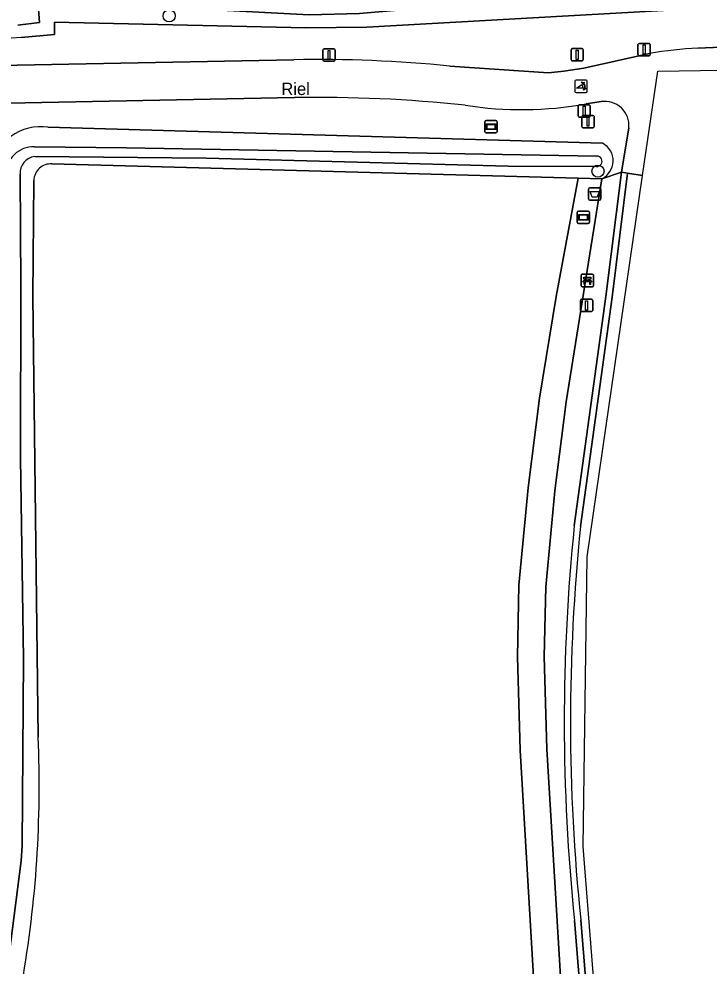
# Model space of a CAD drawing. Extents: x 163426 to 164192, y 380329 to 381641.
# Drawn here: x 164054.4 to 164110, y 380946 to 381022.4 of the extents above; entities that cross this region are included whole.
import ezdxf

# ---------------------------------------------------------------- set-up
doc = ezdxf.new("R2010")
doc.units = 0
for name, color, linetype in [('IMGEO_Afsluitpaal', 7, 'Continuous'), ('IMGEO_Afvalbak', 7, 'Continuous'), ('IMGEO_Bank', 7, 'Continuous'), ('IMGEO_Berm_halfverhard', 7, 'Continuous'), ('IMGEO_Boom', 7, 'Continuous'), ('IMGEO_Erf', 7, 'Continuous'), ('IMGEO_Fietspad_gesloten', 7, 'Continuous'), ('IMGEO_Fietspad_open', 7, 'Continuous'), ('IMGEO_Grasland_overig', 7, 'Continuous'), ('IMGEO_Groenvoorziening', 7, 'Continuous'), ('IMGEO_Informatiebord', 7, 'Continuous'), ('IMGEO_Lichtmast', 7, 'Continuous'), ('IMGEO_Loofbos', 7, 'Continuous'), ('IMGEO_Oever', 7, 'Continuous'), ('IMGEO_Openbare_ruimte_label', 7, 'Continuous'), ('IMGEO_Poller', 7, 'Continuous'), ('IMGEO_Verkeersbordpaal', 7, 'Continuous'), ('IMGEO_Waterloop', 7, 'Continuous'), ('IMGEO_Wegwijzer', 7, 'Continuous')]:
    doc.layers.add(name, color=color, linetype=linetype)

msp = doc.modelspace()

# ---------------------------------------------------------------- linework, layer by layer
at = {"layer": 'IMGEO_Afsluitpaal'}
for p, q in [((164098.925, 381019.065), (164098.925, 381019.865)), ((164098.925, 381019.865), (164098.925, 381019.065)), ((164099.025, 381019.965), (164099.815, 381019.965)), ((164099.815, 381019.965), (164099.025, 381019.965)), ((164099.915, 381019.865), (164099.915, 381019.065)), ((164099.915, 381019.065), (164099.915, 381019.865)), ((164099.815, 381018.965), (164099.025, 381018.965)), ((164099.025, 381018.965), (164099.815, 381018.965)), ((164099.491, 381014.542), (164099.491, 381015.342)), ((164099.491, 381015.342), (164099.491, 381014.542)), ((164099.591, 381015.442), (164100.381, 381015.442)), ((164100.381, 381015.442), (164099.591, 381015.442)), ((164100.481, 381015.342), (164100.481, 381014.542)), ((164100.481, 381014.542), (164100.481, 381015.342)), ((164100.381, 381014.442), (164099.591, 381014.442)), ((164099.591, 381014.442), (164100.381, 381014.442)), ((164099.796, 381013.683), (164099.796, 381014.483)), ((164099.796, 381014.483), (164099.796, 381013.683)), ((164099.896, 381014.583), (164100.686, 381014.583)), ((164100.686, 381014.583), (164099.896, 381014.583)), ((164100.786, 381014.483), (164100.786, 381013.683)), ((164100.786, 381013.683), (164100.786, 381014.483)), ((164100.686, 381013.583), (164099.896, 381013.583)), ((164099.896, 381013.583), (164100.686, 381013.583))]:
    msp.add_line(p, q, dxfattribs=at)
for points in [[(164099.345, 381019.84), (164099.495, 381019.84), (164099.495, 381019.09), (164099.345, 381019.09), (164099.345, 381019.84)], [(164099.911, 381015.317), (164100.061, 381015.317), (164100.061, 381014.567), (164099.911, 381014.567), (164099.911, 381015.317)], [(164100.216, 381014.458), (164100.366, 381014.458), (164100.366, 381013.708), (164100.216, 381013.708), (164100.216, 381014.458)]]:
    msp.add_lwpolyline(points, dxfattribs=at)
for centre, start, end in [((164099.025, 381019.865), 90, 180), ((164099.025, 381019.865), 90, 180), ((164099.815, 381019.865), 0, 90), ((164099.815, 381019.865), 360, 90), ((164099.025, 381019.065), 180, 270), ((164099.025, 381019.065), 180, 270), ((164099.815, 381019.065), 270, 0), ((164099.815, 381019.065), 270, 0), ((164099.591, 381015.342), 90, 180), ((164099.591, 381015.342), 90, 180), ((164100.381, 381015.342), 0, 90), ((164100.381, 381015.342), 360, 90), ((164099.591, 381014.542), 180, 270), ((164099.591, 381014.542), 180, 270), ((164099.896, 381014.483), 90, 180), ((164099.896, 381014.483), 90, 180), ((164100.381, 381014.542), 270, 0), ((164100.381, 381014.542), 270, 0), ((164100.686, 381014.483), 0, 90), ((164100.686, 381014.483), 360, 90), ((164099.896, 381013.683), 180, 270), ((164099.896, 381013.683), 180, 270), ((164100.686, 381013.683), 270, 0), ((164100.686, 381013.683), 270, 0)]:
    msp.add_arc(centre, 0.1, start, end, dxfattribs=at)
at = {"layer": 'IMGEO_Afvalbak'}
for p, q in [((164100.437, 381008.748), (164101.227, 381008.748)), ((164101.227, 381008.748), (164100.437, 381008.748)), ((164100.337, 381007.848), (164100.337, 381008.648)), ((164100.337, 381008.648), (164100.337, 381007.848)), ((164101.327, 381008.648), (164101.327, 381007.848)), ((164101.327, 381007.848), (164101.327, 381008.648)), ((164101.227, 381007.748), (164100.437, 381007.748)), ((164100.437, 381007.748), (164101.227, 381007.748))]:
    msp.add_line(p, q, dxfattribs=at)
msp.add_lwpolyline([(164100.48, 381008.462), (164101.184, 381008.462), (164101.035, 381007.992), (164100.629, 381007.992), (164100.48, 381008.462)], dxfattribs=at)
for centre, start, end in [((164100.437, 381008.648), 90, 180), ((164100.437, 381008.648), 90, 180), ((164101.227, 381008.648), 0, 90), ((164101.227, 381008.648), 360, 90), ((164100.437, 381007.848), 180, 270), ((164100.437, 381007.848), 180, 270), ((164101.227, 381007.848), 270, 0), ((164101.227, 381007.848), 270, 0)]:
    msp.add_arc(centre, 0.1, start, end, dxfattribs=at)
at = {"layer": 'IMGEO_Bank'}
for p, q in [((164099.736, 381000.852), (164099.736, 381001.693)), ((164099.736, 381001.693), (164099.736, 381000.852)), ((164099.811, 381001.777), (164100.652, 381001.777)), ((164100.652, 381001.777), (164099.811, 381001.777)), ((164100.433, 381001.175), (164100.04, 381001.175)), ((164100.045, 381001.283), (164100.045, 381001.389)), ((164100.089, 381001.389), (164100.089, 381001.283)), ((164100.377, 381001.395), (164100.095, 381001.395)), ((164100.095, 381001.277), (164100.377, 381001.277)), ((164100.383, 381001.283), (164100.383, 381001.389)), ((164100.427, 381001.389), (164100.427, 381001.283)), ((164100.736, 381001.702), (164100.736, 381000.861)), ((164100.736, 381000.861), (164100.736, 381001.702)), ((164100.661, 381000.777), (164099.82, 381000.777)), ((164099.82, 381000.777), (164100.661, 381000.777))]:
    msp.add_line(p, q, dxfattribs=at)
for points in [[(164099.983, 381001.175), (164099.841, 381001.175), (164099.953, 381001.277), (164100.039, 381001.277)], [(164100.039, 381001.395), (164099.953, 381001.395), (164099.953, 381001.556), (164100.516, 381001.556), (164100.516, 381001.395), (164100.433, 381001.395)], [(164100.033, 381001.168), (164100.033, 381000.961), (164099.99, 381000.961), (164099.99, 381001.168)], [(164100.433, 381001.277), (164100.516, 381001.277), (164100.628, 381001.175), (164100.489, 381001.175)], [(164100.483, 381001.168), (164100.483, 381000.961), (164100.439, 381000.961), (164100.439, 381001.168)]]:
    msp.add_lwpolyline(points, dxfattribs=at)
for centre, radius, start, end in [((164099.814, 381001.699), 0.0779, 92.4484, 184.28452), ((164099.814, 381001.699), 0.0779, 92.4484, 184.28452), ((164099.983, 381001.168), 0.00671, 2.89567, 87.10433), ((164100.04, 381001.168), 0.00671, 92.89567, 177.10433), ((164100.038, 381001.388), 0.00671, 2.89567, 87.10433), ((164100.038, 381001.284), 0.00671, 272.89567, 357.10433), ((164100.095, 381001.388), 0.00671, 92.89567, 177.10433), ((164100.095, 381001.284), 0.00671, 182.89567, 267.10433), ((164100.377, 381001.388), 0.00671, 2.89567, 87.10433), ((164100.377, 381001.284), 0.00671, 272.89567, 357.10433), ((164100.434, 381001.388), 0.00671, 92.89567, 177.10433), ((164100.434, 381001.284), 0.00671, 182.89567, 267.10433), ((164100.432, 381001.168), 0.00671, 2.89567, 87.10433), ((164100.489, 381001.168), 0.00671, 92.89567, 177.10433), ((164100.658, 381001.699), 0.0779, 2.4484, 94.28452), ((164100.658, 381001.699), 0.0779, 2.4484, 94.28452), ((164099.814, 381000.855), 0.0779, 182.4484, 274.28452), ((164099.814, 381000.855), 0.0779, 182.4484, 274.28452), ((164100.658, 381000.855), 0.0779, 272.4484, 4.28452), ((164100.658, 381000.855), 0.0779, 272.4484, 4.28452)]:
    msp.add_arc(centre, radius, start, end, dxfattribs=at)
at = {"layer": 'IMGEO_Berm_halfverhard'}
for points in [[(164103.481, 381009.921), (164102.986, 381009.995), (164101.733, 381000), (164099.191, 380981.518)], [(164099.688, 380981.458), (164102.229, 380999.935), (164103.481, 381009.921)], [(164099.211, 380949.707), (164103.3, 380899.159)], [(164103.948, 380897.352), (164099.709, 380949.759)]]:
    msp.add_lwpolyline(points, dxfattribs=at)
for centre, radius, start, end in [((164253.428, 380965.709), 155.045, 174.14791, 185.92414), ((164253.311, 380965.71), 154.428, 174.1471, 185.92881)]:
    msp.add_arc(centre, radius, start, end, dxfattribs=at)
at = {"layer": 'IMGEO_Boom'}
for centre in [(164066.54, 381022.596), (164101.097, 381010.08)]:
    msp.add_circle(centre, 0.489, dxfattribs=at)
at = {"layer": 'IMGEO_Erf'}
msp.add_lwpolyline([(164054.357, 381021.851), (164056.102, 381022.069), (164055.954, 381023.839), (164077.832, 381022.685), (164081.887, 381022.792), (164085.928, 381023.151), (164130.664, 381025.955), (164127.903, 381058.65)], dxfattribs=at)
at = {"layer": 'IMGEO_Fietspad_gesloten'}
for points in [[(164048.055, 380721.757), (164102.115, 380870.192), (164105.202, 380888.906), (164099.896, 380955.658), (164100.234, 380979.002), (164104.697, 381009.739), (164103.481, 381009.921), (164102.229, 380999.935), (164099.688, 380981.458)], [(164099.709, 380949.759), (164103.948, 380897.352)]]:
    msp.add_lwpolyline(points, dxfattribs=at)
msp.add_arc((164253.311, 380965.71), 154.428, 174.1471, 185.92881, dxfattribs=at)
at = {"layer": 'IMGEO_Fietspad_open'}
for points in [[(164104.697, 381009.739), (164105.917, 381018.14), (164138.479, 381018.661), (164138.461, 381019.094), (164138.376, 381021.103), (164138.37, 381021.245), (164137.275, 381021.187), (164132.414, 381020.981), (164109.15, 381019.998)], [(164105.262, 381019.567), (164099.961, 381018.375), (164098.342, 381018.136), (164097.12, 381018.022), (164089.169, 381018.552)], [(164076.579, 381019.063), (164051.479, 381018.565)], [(164050.323, 381015.504), (164050.83, 381015.503), (164076.638, 381016.014)], [(164100.133, 381015.513), (164101.354, 381015.692)], [(164103.584, 381013.587), (164102.986, 381009.995), (164103.481, 381009.921), (164104.697, 381009.739)]]:
    msp.add_lwpolyline(points, dxfattribs=at)
for centre, radius, start, end in [((164110.451, 380990.512), 29.515, 92.52596, 100.12531), ((164078.612, 380913.798), 105.284, 84.24516, 91.10638), ((164078.488, 380902.035), 113.994, 84.00222, 90.92978), ((164101.641, 381013.762), 1.951, 354.85069, 98.45265), ((164094.952, 381043.791), 28.748, 260.88814, 280.38321)]:
    msp.add_arc(centre, radius, start, end, dxfattribs=at)
at = {"layer": 'IMGEO_Grasland_overig'}
for points in [[(164099.191, 380981.518), (164101.733, 381000), (164102.986, 381009.995), (164101.403, 381009.478), (164098.529, 380991.495), (164097.634, 380984.323), (164096.895, 380976.605), (164096.774, 380970.972), (164096.987, 380963.514), (164098.451, 380938.932), (164101.024, 380906.239), (164101.783, 380892.023), (164101.86, 380886.91), (164101.73, 380881.332), (164101.499, 380879.655), (164099.402, 380880.35), (164098.657, 380877.436), (164100.816, 380876.721), (164099.342, 380871.356), (164097.621, 380866.657), (164087.66, 380841.86), (164064.262, 380778.046), (164040.28, 380713.821)], [(164103.3, 380899.159), (164099.211, 380949.707)]]:
    msp.add_lwpolyline(points, dxfattribs=at)
msp.add_arc((164253.428, 380965.709), 155.045, 174.14791, 185.92414, dxfattribs=at)
at = {"layer": 'IMGEO_Groenvoorziening'}
for points in [[(164109.15, 381019.998), (164132.414, 381020.981), (164133.36, 381022.885), (164133.351, 381023.134), (164133.225, 381024.655), (164131.208, 381024.463), (164082.482, 381021.699), (164077.549, 381021.635), (164057.316, 381022.101), (164057.296, 381021.095), (164054.628, 381020.862)], [(164089.169, 381018.552), (164097.12, 381018.022), (164098.342, 381018.136), (164099.961, 381018.375), (164105.262, 381019.567)], [(164051.479, 381018.565), (164076.579, 381019.063)], [(164076.638, 381016.014), (164050.83, 381015.503), (164050.855, 381010.828), (164050.906, 381000), (164051.075, 380964.76), (164051.149, 380955.68), (164047.573, 380932.485), (164044.028, 380904.553), (164043.903, 380903.564), (164044.304, 380902.982), (164050.569, 380946.036)], [(164101.354, 381015.692), (164100.133, 381015.513)], [(164056.78, 381013.624), (164101.472, 381012.331)], [(164101.403, 381009.478), (164102.986, 381009.995), (164103.584, 381013.587)], [(164101.783, 380892.023), (164101.024, 380906.239), (164098.451, 380938.932), (164096.987, 380963.514), (164096.774, 380970.972), (164096.895, 380976.605), (164097.634, 380984.323), (164098.529, 380991.495), (164101.403, 381009.478), (164099.5, 381009.518), (164097.728, 381000), (164096.379, 380991.806), (164095.475, 380984.561), (164094.726, 380976.732), (164094.602, 380970.964), (164094.817, 380963.419), (164096.284, 380938.782), (164098.857, 380906.096), (164099.568, 380892.777)]]:
    msp.add_lwpolyline(points, dxfattribs=at)
for centre, radius, start, end in [((164063.698, 380870.896), 150.24, 93.46108, 107.59041), ((164110.451, 380990.512), 29.515, 92.52596, 100.12531), ((164078.612, 380913.798), 105.284, 84.24516, 91.10638), ((164078.488, 380902.035), 113.994, 84.00222, 90.92978), ((164101.641, 381013.762), 1.951, 354.85069, 98.45265), ((164094.952, 381043.791), 28.748, 260.88814, 280.38321), ((164056.179, 381009.686), 3.984, 81.32229, 172.20759), ((164100.732, 381010.922), 1.592, 294.91875, 62.31038)]:
    msp.add_arc(centre, radius, start, end, dxfattribs=at)
at = {"layer": 'IMGEO_Informatiebord'}
for p, q in [((164099.422, 381005.965), (164099.422, 381006.765)), ((164099.422, 381006.765), (164099.422, 381005.965)), ((164099.522, 381006.865), (164100.312, 381006.865)), ((164100.312, 381006.865), (164099.522, 381006.865)), ((164100.412, 381006.765), (164100.412, 381005.965)), ((164100.412, 381005.965), (164100.412, 381006.765)), ((164100.312, 381005.865), (164099.522, 381005.865)), ((164099.522, 381005.865), (164100.312, 381005.865))]:
    msp.add_line(p, q, dxfattribs=at)
for points in [[(164099.523, 381006.597), (164100.311, 381006.597), (164100.311, 381006.133), (164099.523, 381006.133), (164099.523, 381006.597)], [(164099.588, 381006.532), (164099.588, 381006.198), (164100.246, 381006.198), (164100.246, 381006.532), (164099.588, 381006.532)]]:
    msp.add_lwpolyline(points, dxfattribs=at)
for centre, start, end in [((164099.522, 381006.765), 90, 180), ((164099.522, 381006.765), 90, 180), ((164100.312, 381006.765), 0, 90), ((164100.312, 381006.765), 360, 90), ((164099.522, 381005.965), 180, 270), ((164099.522, 381005.965), 180, 270), ((164100.312, 381005.965), 270, 0), ((164100.312, 381005.965), 270, 0)]:
    msp.add_arc(centre, 0.1, start, end, dxfattribs=at)
at = {"layer": 'IMGEO_Lichtmast'}
for p, q in [((164104.321, 381019.484), (164104.321, 381020.284)), ((164104.321, 381020.284), (164104.321, 381019.484)), ((164104.421, 381020.384), (164105.211, 381020.384)), ((164105.211, 381020.384), (164104.421, 381020.384)), ((164105.311, 381020.284), (164105.311, 381019.484)), ((164105.311, 381019.484), (164105.311, 381020.284)), ((164078.934, 381019.047), (164078.934, 381019.847)), ((164078.934, 381019.847), (164078.934, 381019.047)), ((164079.034, 381019.947), (164079.824, 381019.947)), ((164079.824, 381019.947), (164079.034, 381019.947)), ((164079.924, 381019.847), (164079.924, 381019.047)), ((164079.924, 381019.047), (164079.924, 381019.847)), ((164079.824, 381018.947), (164079.034, 381018.947)), ((164079.034, 381018.947), (164079.824, 381018.947)), ((164105.211, 381019.384), (164104.421, 381019.384)), ((164104.421, 381019.384), (164105.211, 381019.384))]:
    msp.add_line(p, q, dxfattribs=at)
for points in [[(164104.741, 381020.259), (164104.891, 381020.259), (164104.891, 381019.509), (164104.741, 381019.509), (164104.741, 381020.259)], [(164079.354, 381019.822), (164079.504, 381019.822), (164079.504, 381019.072), (164079.354, 381019.072), (164079.354, 381019.822)]]:
    msp.add_lwpolyline(points, dxfattribs=at)
for centre, start, end in [((164104.421, 381020.284), 90, 180), ((164104.421, 381020.284), 90, 180), ((164105.211, 381020.284), 0, 90), ((164105.211, 381020.284), 360, 90), ((164079.034, 381019.847), 90, 180), ((164079.034, 381019.847), 90, 180), ((164079.824, 381019.847), 0, 90), ((164079.824, 381019.847), 360, 90), ((164104.421, 381019.484), 180, 270), ((164104.421, 381019.484), 180, 270), ((164105.211, 381019.484), 270, 0), ((164105.211, 381019.484), 270, 0), ((164079.034, 381019.047), 180, 270), ((164079.034, 381019.047), 180, 270), ((164079.824, 381019.047), 270, 0), ((164079.824, 381019.047), 270, 0)]:
    msp.add_arc(centre, 0.1, start, end, dxfattribs=at)
at = {"layer": 'IMGEO_Loofbos'}
for points in [[(164094.817, 380963.419), (164094.602, 380970.964), (164094.726, 380976.732), (164095.475, 380984.561), (164096.379, 380991.806), (164097.728, 381000), (164099.5, 381009.518), (164057.103, 381010.673)], [(164055.645, 381009.343), (164055.565, 381000), (164055.987, 380964.49)], [(164054.694, 380944.678), (164047.153, 380897.669), (164058.918, 380895.419), (164073.794, 380892.938), (164079.473, 380892.61), (164086.687, 380892.194), (164099.568, 380892.777), (164098.857, 380906.096), (164096.284, 380938.782), (164094.817, 380963.419)]]:
    msp.add_lwpolyline(points, dxfattribs=at)
for centre, radius, start, end in [((164057.008, 381009.313), 1.363, 86.00383, 178.73884), ((163964.832, 380960.491), 91.243, 350.01993, 2.51202)]:
    msp.add_arc(centre, radius, start, end, dxfattribs=at)
at = {"layer": 'IMGEO_Oever'}
for points in [[(164101.472, 381012.331), (164056.78, 381013.624)], [(164055.686, 381012.056), (164063.119, 381011.974), (164100.984, 381011.296)], [(164100.958, 381010.475), (164093.853, 381010.496), (164069.52, 381011.132), (164055.722, 381011.276)], [(164057.103, 381010.673), (164099.5, 381009.518), (164101.403, 381009.478)], [(164054.531, 381009.839), (164054.592, 381000.886), (164054.572, 380986.964), (164054.818, 380970.783), (164054.695, 380955.711), (164054.613, 380954.52), (164052.929, 380941.296), (164050.629, 380926.943), (164048.699, 380913.843), (164046.707, 380901.338)], [(164055.987, 380964.49), (164055.565, 381000), (164055.645, 381009.343)]]:
    msp.add_lwpolyline(points, dxfattribs=at)
for centre, radius, start, end in [((164056.179, 381009.686), 3.984, 81.32229, 172.20759), ((164055.625, 381009.817), 2.239, 88.43944, 178.93639), ((164100.732, 381010.922), 1.592, 294.91875, 62.31038), ((164055.909, 381009.909), 1.38, 97.79597, 182.89947), ((164101.019, 381010.884), 0.413, 261.54895, 94.8233), ((164057.008, 381009.313), 1.363, 86.00383, 178.73884), ((163964.832, 380960.491), 91.243, 350.01993, 2.51202)]:
    msp.add_arc(centre, radius, start, end, dxfattribs=at)
at = {"layer": 'IMGEO_Poller'}
for p, q in [((164099.24, 381017.335), (164099.24, 381016.528)), ((164099.24, 381017.335), (164099.24, 381016.528)), ((164100.142, 381017.43), (164099.334, 381017.43)), ((164100.142, 381017.43), (164099.334, 381017.43)), ((164100.236, 381016.528), (164100.236, 381017.335)), ((164100.236, 381016.528), (164100.236, 381017.335)), ((164099.334, 381016.433), (164100.142, 381016.433)), ((164099.334, 381016.433), (164100.142, 381016.433))]:
    msp.add_line(p, q, dxfattribs=at)
for points in [[(164099.919, 381017.159), (164099.907, 381017.086), (164099.782, 381017.291)], [(164099.782, 381017.291), (164100.013, 381017.225), (164099.942, 381017.193)], [(164099.875, 381016.786), (164099.362, 381016.786), (164099.792, 381017.061)], [(164099.935, 381016.614), (164100.001, 381016.845), (164100.031, 381016.777)], [(164100.067, 381016.75), (164100.139, 381016.739), (164099.935, 381016.614)]]:
    msp.add_lwpolyline(points, dxfattribs=at)
for centre, radius, start, end in [((164099.334, 381017.335), 0.0946, 90, 180), ((164099.334, 381017.335), 0.0946, 90, 180), ((164099.561, 381016.846), 0.476, 351.75274, 41.16905), ((164099.561, 381016.846), 0.516, 349.35686, 42.29123), ((164100.142, 381017.335), 0.0946, 0, 90), ((164100.142, 381017.335), 0.0946, 0, 90), ((164099.334, 381016.528), 0.0946, 180, 270), ((164099.334, 381016.528), 0.0946, 180, 270), ((164099.547, 381016.836), 0.332, 351.32473, 42.4854), ((164100.142, 381016.528), 0.0946, 270, 0), ((164100.142, 381016.528), 0.0946, 270, 0)]:
    msp.add_arc(centre, radius, start, end, dxfattribs=at)
at = {"layer": 'IMGEO_Verkeersbordpaal'}
for p, q in [((164099.681, 380998.868), (164099.681, 380999.668)), ((164099.681, 380999.668), (164099.681, 380998.868)), ((164099.781, 380999.768), (164100.571, 380999.768)), ((164100.571, 380999.768), (164099.781, 380999.768)), ((164100.671, 380999.668), (164100.671, 380998.868)), ((164100.671, 380998.868), (164100.671, 380999.668)), ((164100.571, 380998.768), (164099.781, 380998.768)), ((164099.781, 380998.768), (164100.571, 380998.768))]:
    msp.add_line(p, q, dxfattribs=at)
msp.add_lwpolyline([(164100.101, 380999.643), (164100.251, 380999.643), (164100.251, 380998.893), (164100.101, 380998.893), (164100.101, 380999.643)], dxfattribs=at)
for centre, start, end in [((164099.781, 380999.668), 90, 180), ((164099.781, 380999.668), 90, 180), ((164100.571, 380999.668), 0, 90), ((164100.571, 380999.668), 360, 90), ((164099.781, 380998.868), 180, 270), ((164099.781, 380998.868), 180, 270), ((164100.571, 380998.868), 270, 0), ((164100.571, 380998.868), 270, 0)]:
    msp.add_arc(centre, 0.1, start, end, dxfattribs=at)
at = {"layer": 'IMGEO_Waterloop'}
for points in [[(164054.628, 381020.862), (164057.296, 381021.095), (164057.316, 381022.101), (164077.549, 381021.635), (164082.482, 381021.699), (164131.208, 381024.463), (164131.108, 381025.22), (164131.009, 381025.977), (164130.664, 381025.955), (164085.928, 381023.151), (164081.887, 381022.792), (164077.832, 381022.685), (164055.954, 381023.839), (164056.102, 381022.069), (164054.357, 381021.851)], [(164100.984, 381011.296), (164063.119, 381011.974), (164055.686, 381012.056)], [(164055.722, 381011.276), (164069.52, 381011.132), (164093.853, 381010.496), (164100.958, 381010.475)], [(164046.707, 380901.338), (164048.699, 380913.843), (164050.629, 380926.943), (164052.929, 380941.296), (164054.613, 380954.52), (164054.695, 380955.711), (164054.818, 380970.783), (164054.572, 380986.964), (164054.592, 381000.886), (164054.531, 381009.839)]]:
    msp.add_lwpolyline(points, dxfattribs=at)
for centre, radius, start, end in [((164063.698, 380870.896), 150.24, 93.46108, 107.59041), ((164055.625, 381009.817), 2.239, 88.43944, 178.93639), ((164055.909, 381009.909), 1.38, 97.79597, 182.89947), ((164101.019, 381010.884), 0.413, 261.54895, 94.8233)]:
    msp.add_arc(centre, radius, start, end, dxfattribs=at)
at = {"layer": 'IMGEO_Wegwijzer'}
for p, q in [((164092.086, 381014.164), (164092.876, 381014.164)), ((164092.876, 381014.164), (164092.086, 381014.164)), ((164091.986, 381013.264), (164091.986, 381014.064)), ((164091.986, 381014.064), (164091.986, 381013.264)), ((164092.976, 381014.064), (164092.976, 381013.264)), ((164092.976, 381013.264), (164092.976, 381014.064)), ((164092.876, 381013.164), (164092.086, 381013.164)), ((164092.086, 381013.164), (164092.876, 381013.164))]:
    msp.add_line(p, q, dxfattribs=at)
for points in [[(164092.087, 381013.896), (164092.875, 381013.896), (164092.875, 381013.432), (164092.087, 381013.432), (164092.087, 381013.896)], [(164092.152, 381013.831), (164092.152, 381013.497), (164092.81, 381013.497), (164092.81, 381013.831), (164092.152, 381013.831)]]:
    msp.add_lwpolyline(points, dxfattribs=at)
for centre, start, end in [((164092.086, 381014.064), 90, 180), ((164092.086, 381014.064), 90, 180), ((164092.876, 381014.064), 0, 90), ((164092.876, 381014.064), 360, 90), ((164092.086, 381013.264), 180, 270), ((164092.086, 381013.264), 180, 270), ((164092.876, 381013.264), 270, 0), ((164092.876, 381013.264), 270, 0)]:
    msp.add_arc(centre, 0.1, start, end, dxfattribs=at)

# ---------------------------------------------------------------- texts
at = {"layer": 'IMGEO_Openbare_ruimte_label'}
msp.add_text('Riel', height=1, rotation=0.34377, dxfattribs=at).set_placement((164075.585, 381016.211))

doc.saveas('drawing.dxf')
